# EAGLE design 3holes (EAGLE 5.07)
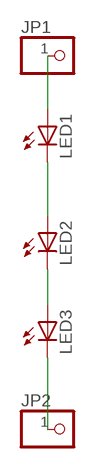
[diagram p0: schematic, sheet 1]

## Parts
JP1  PINHD-1X11MM6  [1X1MM8]
JP2  PINHD-1X11MM6  [1X1MM8]
LED1  LED1W_HOLE  [1W]
LED2  LED1W_HOLE  [1W]
LED3  LED1W_HOLE  [1W]

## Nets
N$1: LED1.C LED2.A
N$2: LED2.C LED3.A
N$3: JP1.1 LED1.A
N$4: JP2.1 LED3.C

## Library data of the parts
JP1 JP2 = pinhead:PINHD-1X1: PIN HEADER
LED1-LED3 = led:LED: LED

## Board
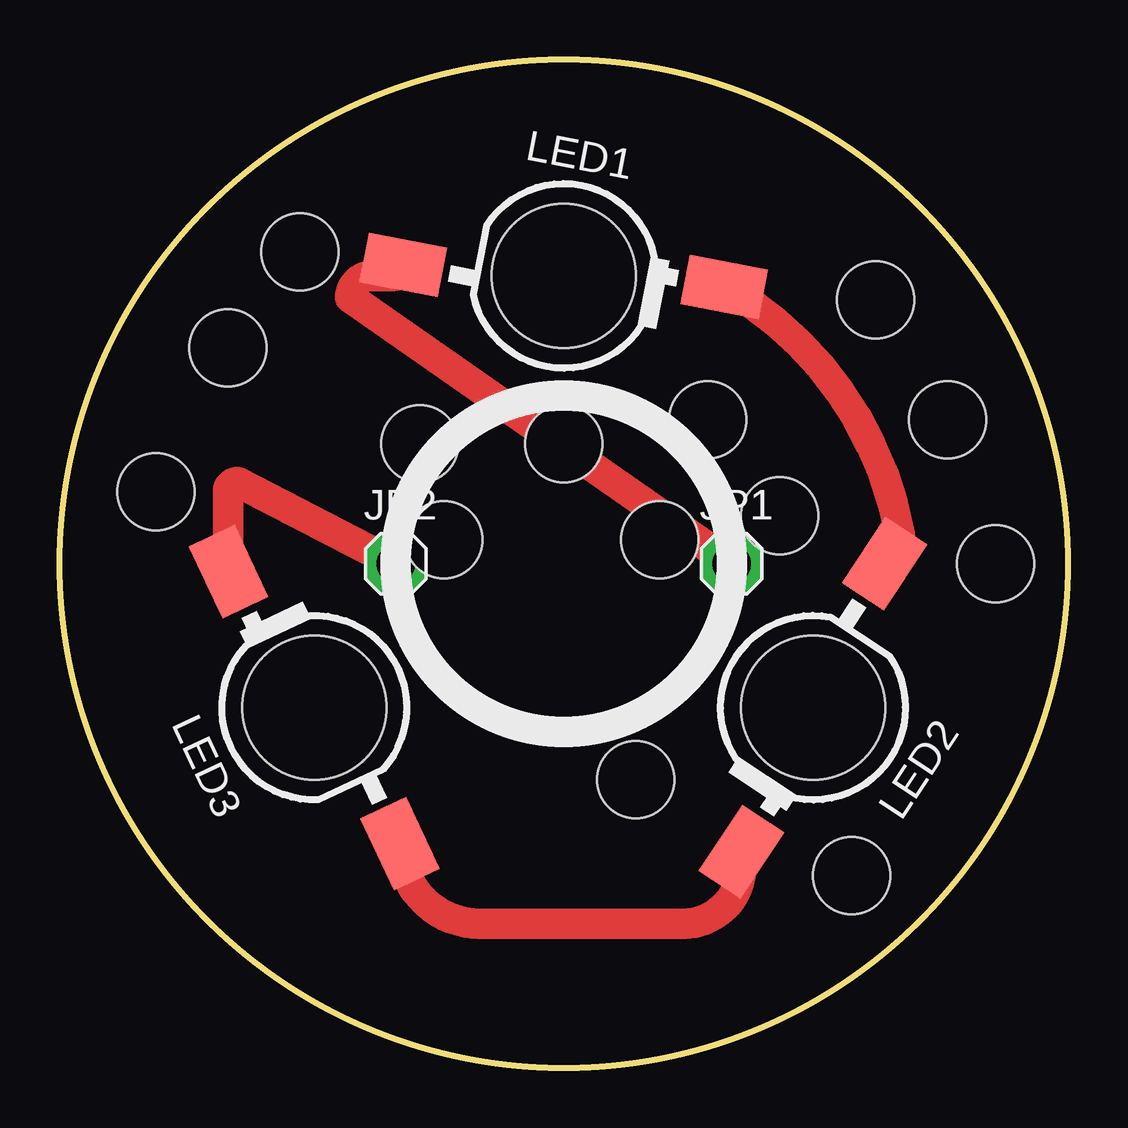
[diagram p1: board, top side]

Size 42 x 42 mm. Coordinates in mm from the lower left corner, seen from the top.
Outline: circle at 21,21 radius 21
Copper layers (1*16): Top 0.035mm / dielectric 1.5mm / Bottom 0.035mm
Design rules "default": minimum track width 10mil, minimum drill 24mil, track to track 8mil, track to pad 8mil, pad to pad 8mil, via to via 8mil, smd to smd 8mil, copper to edge 40mil, drill to drill 8mil, minimum pad ring 10mil, minimum via ring 8mil, stop-mask expansion 4mil, vias tented up to drill 0mil, thermal gap 10mil
Holes 3.2 mm at 25,22 21,26 16,22 30,23 34,32 37,27 39,21 33,8 24,12 15,26 27,27 7,30 4,24 10,34

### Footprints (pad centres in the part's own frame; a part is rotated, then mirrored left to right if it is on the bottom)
1X1MM8 = drill 1.6 pad 2.54 octagon: 1 0,0
1W = smd 3.3 x 2.1: A -6.65,-0.82; C 6.65,0.82 | hole 6: 0,0

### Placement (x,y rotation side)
JP1  28,21 0 top
JP2  14,21 0 top
LED1  21,33 349.1 top
LED2  31.39,15 236.5 top
LED3  10.6,15 115.2 top

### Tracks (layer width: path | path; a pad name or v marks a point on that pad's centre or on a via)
N$1
  Top 0.406: 35,22.23 35,22 arc90 34.38,21.38 LED2.A
  Top 1.27: 35,22.23 arc50 LED1.C
N$2
  Top 1.27: LED3.A arc90 17.5,6 26,6 arc90 28.4,8.4 LED2.C
N$3
  Top 1.27: JP1.1 12.1,32.1 arc-90 13,33 13.86,33 arc90 LED1.A
N$4
  Top 1.27: LED3.C arc-90 7,20.7 7,24 arc-90 7.4,24.4 JP2.1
